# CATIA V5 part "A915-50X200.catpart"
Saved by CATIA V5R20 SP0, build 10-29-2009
Part number: A915-50X200
Source: Unknown
Property "A": "0.000"
Property "ARTICLENO": "A915-50X200"
Property "BOMINFO": "A915-50X200"
Property "CODE": "A915-50X200"
Property "CREATOR": "CADENAS GmbH"
Property "D": "13.500"
Property "D1": "20.000"
Property "FORM": "B"
Property "L": "200.000"
Property "L1": "25.000"
Property "L2": "150.000"
Property "LINA": "A915-50X200"
Property "NB": "A915-50X200"
Property "NBSYN": "$CODE."
Property "NN": "A915"
Property "NT": "VDI 3357 Wear Plates, steel"
Property "SCREW": "M12x25"
Property "SUPPLIER": "CF"
Property "T": "13.000"
Property "W": "50.000"
Bounding box of the stored display mesh (mm): x 0 to 20, y 0 to 200, z -25 to 25
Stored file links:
  C:\Users\borellobunino\Desktop\3D X SITO CF\A915\GSB_OILLESS_G22501050200\A915-50X200.catpart
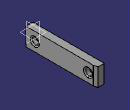
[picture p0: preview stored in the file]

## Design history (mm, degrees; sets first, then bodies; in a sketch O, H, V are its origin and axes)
Body1 "Geometry.1" (main body)
  Solid1 "A915-50X200.catpart": solid without history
